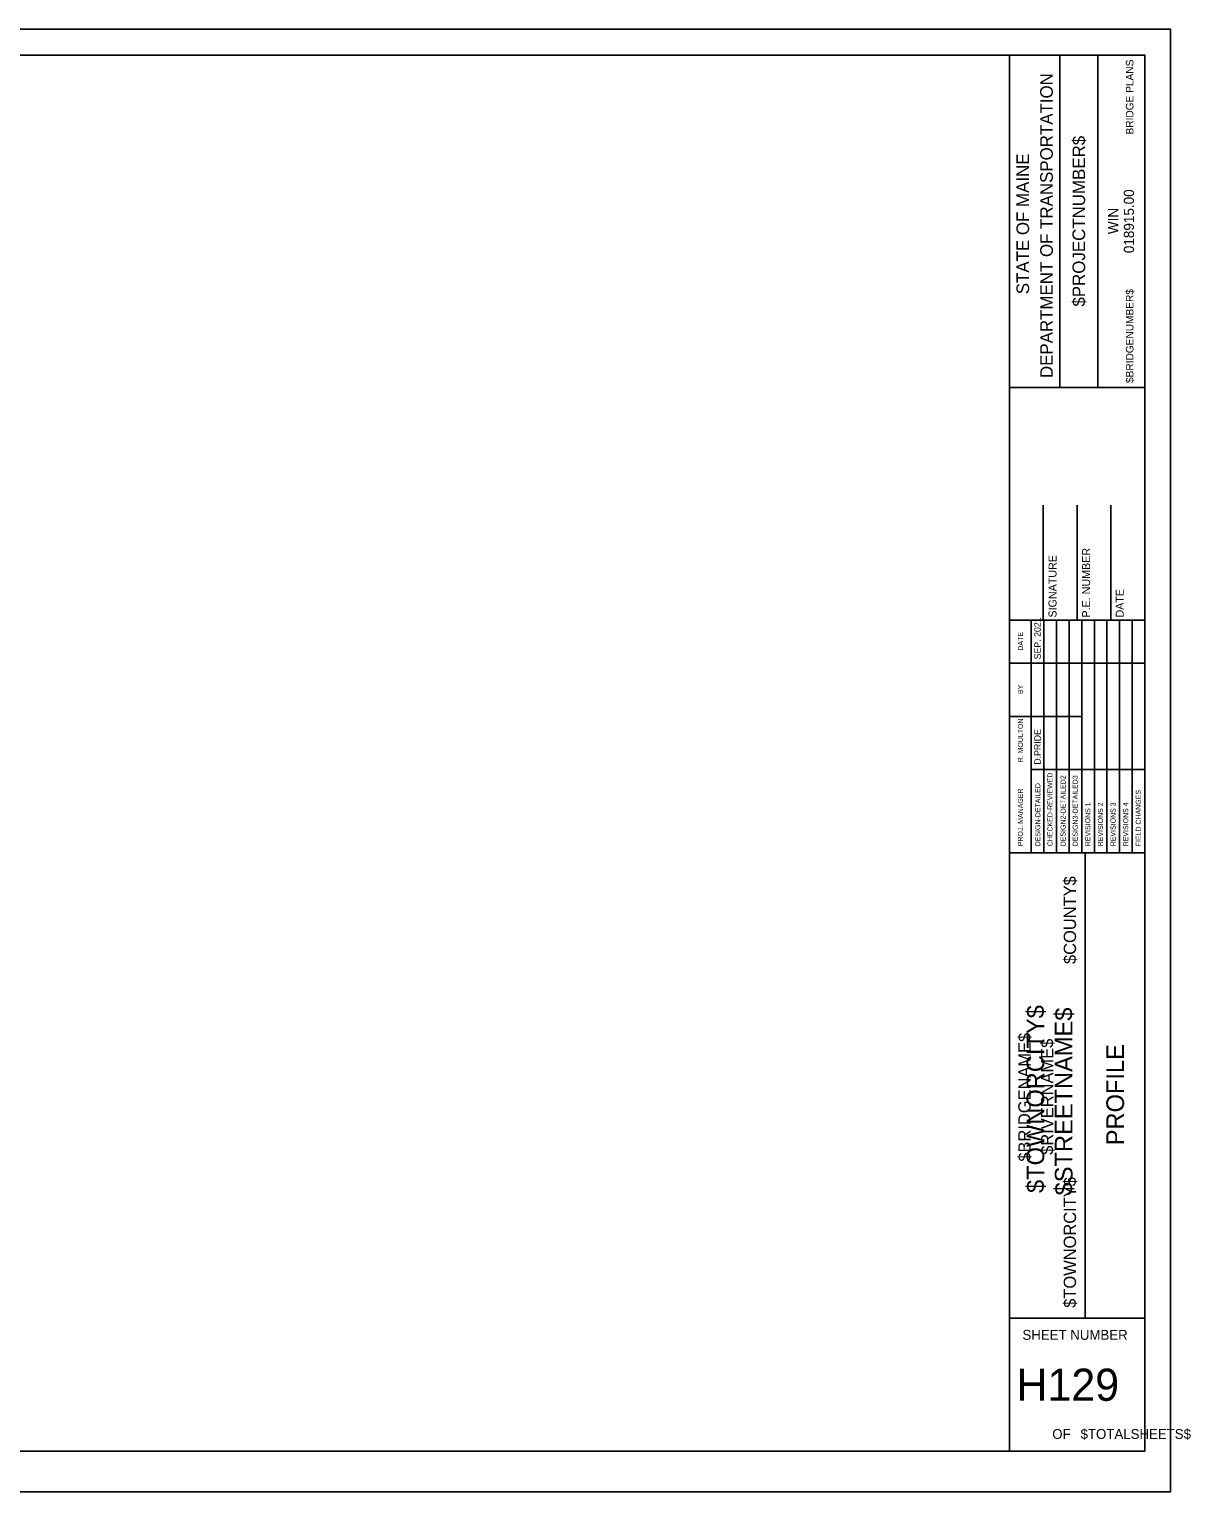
# Model space of a CAD drawing. Extents: x 9960 to 10817, y 9985 to 10525.
# Drawn here: x 10388 to 10817, y 9985 to 10525 of the extents above; entities that cross this region are included whole.
import ezdxf

# ---------------------------------------------------------------- set-up
doc = ezdxf.new("R2010")
doc.units = 0
for name, color, linetype in [('BORDER', 7, 'Continuous'), ('BRIDGE_TITLE', 7, 'Continuous'), ('CLIPS', 7, 'Continuous'), ('HIGHWAY_TITLE', 7, 'Continuous'), ('PLOT BOUNDARY', 7, 'Continuous')]:
    doc.layers.add(name, color=color, linetype=linetype)

msp = doc.modelspace()

# ---------------------------------------------------------------- linework, layer by layer
at = {"layer": 'BORDER'}
for p, q in [((10750, 10000), (10750, 10515)), ((10768.64, 10392.37), (10768.64, 10514.99)), ((10782.62, 10392.37), (10782.62, 10514.99)), ((10750, 10392.35), (10800, 10392.35)), ((10762.5, 10306.56), (10762.5, 10348.98)), ((10775, 10306.56), (10775, 10348.98)), ((10787.5, 10306.56), (10787.5, 10348.98)), ((10750, 10306.56), (10800, 10306.56)), ((10750, 10220.73), (10800, 10220.73)), ((10777.96, 10049.06), (10777.96, 10220.73)), ((10750, 10049.06), (10800, 10049.06))]:
    msp.add_line(p, q, dxfattribs=at)
msp.add_lwpolyline([(10000, 10515), (10800, 10515), (10800, 10000), (10000, 10000)], close=True, dxfattribs=at)
for points in [[(10758.07, 10290.62), (10758.07, 10306.56)], [(10762.74, 10220.74), (10762.74, 10306.56)], [(10767.4, 10306.56), (10767.4, 10220.74)], [(10772.05, 10220.74), (10772.05, 10306.56)], [(10776.71, 10220.74), (10776.71, 10306.56)], [(10781.37, 10220.74), (10781.37, 10306.56)], [(10786.03, 10220.74), (10786.03, 10306.56)], [(10790.69, 10220.74), (10790.69, 10306.56)], [(10795.35, 10220.74), (10795.35, 10306.56)], [(10758.08, 10220.74), (10758.08, 10303.1)], [(10750, 10290.62), (10800, 10290.62)], [(10750, 10271), (10758.08, 10271)], [(10758.07, 10271), (10776.71, 10271)], [(10758.07, 10251.38), (10800, 10251.38)]]:
    msp.add_lwpolyline(points, dxfattribs=at)
at = {"layer": 'CLIPS'}
msp.add_lwpolyline([(10000, 10000), (10750, 10000), (10750, 10515), (10000, 10515)], close=True, dxfattribs=at)
at = {"layer": 'PLOT BOUNDARY'}
msp.add_lwpolyline([(9959.53, 9985), (10809.53, 9985), (10809.53, 10524.52), (9959.53, 10524.52)], close=True, dxfattribs=at)

# ---------------------------------------------------------------- texts
at = {"layer": 'BORDER'}
for s, height, rotation, p in [('DEPARTMENT OF TRANSPORTATION', 4.6588, 90, (10766.03, 10395.84)), ('$PROJECTNUMBER$', 4.6588, 90, (10777.96, 10422.2)), ('STATE OF MAINE', 4.6588, 90, (10757.28, 10426.77)), ('018915.00', 3.726, 90, (10795.98, 10441.91)), ('WIN', 3.726, 90, (10790.18, 10448.93)), ('P.E. NUMBER', 2.9528, 90, (10779.8, 10307.5)), ('SIGNATURE', 2.953, 90, (10767.4, 10307.5)), ('DATE', 2.953, 90, (10792.21, 10307.5)), ('SEP. 2021', 2.423, 90, (10761.61, 10292.07)), ('DATE', 1.857, 90, (10755.02, 10295.31)), ('BY', 1.857, 90, (10755.02, 10279.27)), ('R. MOULTON', 1.864, 90, (10755.02, 10254.09)), ('D.PRIDE', 2.423, 90, (10761.61, 10253.21)), ('DESIGN-DETAILED', 1.8637, 90, (10761.43, 10223.12)), ('CHECKED-REVIEWED', 1.8637, 90, (10765.91, 10223.12)), ('DESIGN2-DETAILED2', 1.8637, 90, (10770.75, 10223.12)), ('DESIGN3-DETAILED3', 1.8637, 90, (10775.22, 10223.12)), ('PROJ. MANAGER', 1.8637, 90, (10755.02, 10223.12)), ('FIELD CHANGES', 1.8637, 90, (10798.51, 10223.12)), ('REVISIONS 1', 1.8637, 90, (10779.88, 10223.12)), ('REVISIONS 2', 1.8637, 90, (10784.54, 10223.12)), ('REVISIONS 3', 1.8637, 90, (10789.2, 10223.12)), ('REVISIONS 4', 1.8637, 90, (10793.86, 10223.12)), ('PROFILE', 6.521, 90, (10792.32, 10112.81)), ('SHEET NUMBER', 3.6554, 360, (10754.83, 10041.04)), ('OF', 3.655, 360, (10765.83, 10004.48)), ('$TOTALSHEETS$', 3.6554, 360, (10776.28, 10004.48))]:
    msp.add_text(s, height=height, rotation=rotation, dxfattribs=at).set_placement(p)
msp.add_text('H129', height=11.867, dxfattribs=at).set_placement((10752.58, 10018.55))
at = {"layer": 'BRIDGE_TITLE'}
for s, height, p in [('BRIDGE PLANS', 2.795, (10795.79, 10485.69)), ('$BRIDGENUMBER$', 2.795, (10795.79, 10394)), ('$COUNTY$', 4.536, (10774.6, 10179.69)), ('$BRIDGENAME$', 4.5358, (10757.83, 10106.78)), ('$RIVERNAME$', 4.5358, (10766.22, 10109.31)), ('$TOWNORCITY$', 4.5358, (10774.6, 10052.86))]:
    msp.add_text(s, height=height, rotation=90, dxfattribs=at).set_placement(p)
at = {"layer": 'HIGHWAY_TITLE'}
for s, p in [('$TOWNORCITY$', (10762.86, 10095.21)), ('$STREETNAME$', (10773.3, 10094.32))]:
    msp.add_text(s, height=6.5214, rotation=90, dxfattribs=at).set_placement(p)

doc.saveas('drawing.dxf')
